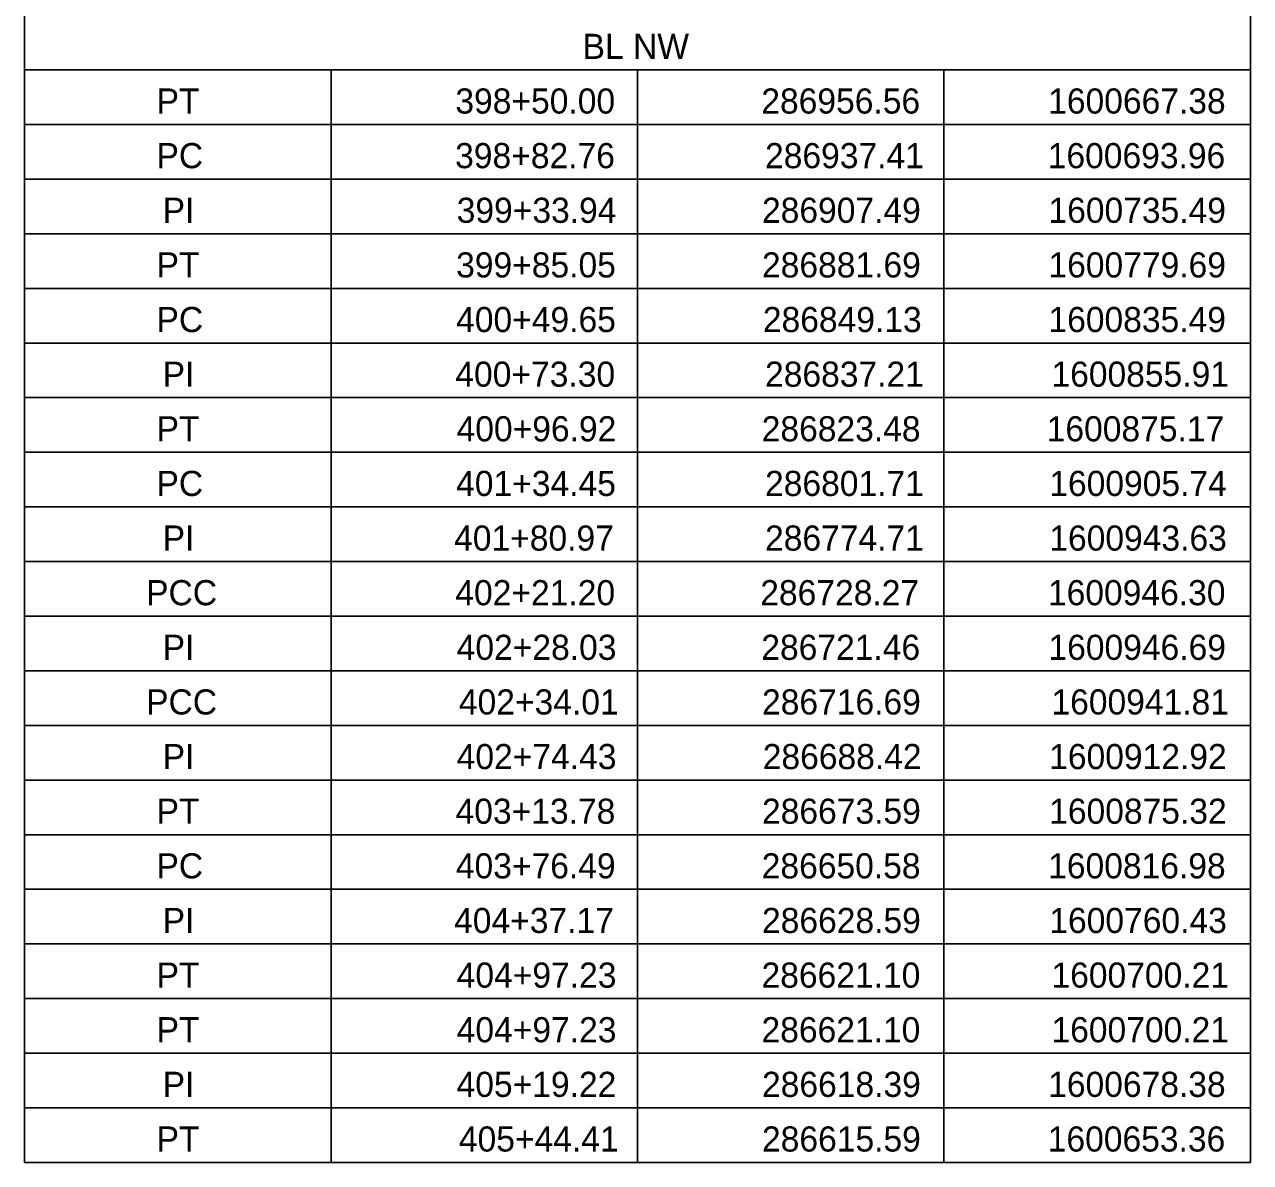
# Model space of a CAD drawing. Extents: x 0 to 34, y 0 to 22.
# Drawn here: x 9.33 to 16.16, y 7.8 to 14.14 of the extents above; entities that cross this region are included whole.
import ezdxf

# ---------------------------------------------------------------- set-up
doc = ezdxf.new("R2010")
doc.units = 0
doc.layers.add('SH_Text', color=7, linetype='Continuous')

msp = doc.modelspace()

# ---------------------------------------------------------------- linework, layer by layer
at = {"layer": 'SH_Text'}
for p, q in [((9.3309, 15.1087), (9.3309, 13.2826)), ((16.1618, 15.1087), (16.1618, 13.2826)), ((9.3309, 13.8913), (16.1618, 13.8913)), ((11.0386, 13.8913), (11.0386, 13.2826)), ((12.7464, 13.8913), (12.7464, 13.2826)), ((14.4541, 13.8913), (14.4541, 13.2826)), ((9.3309, 13.587), (16.1618, 13.587)), ((9.3309, 13.2826), (16.1618, 13.2826)), ((9.3309, 13.2826), (9.3309, 12.9783)), ((11.0386, 13.2826), (11.0386, 12.9783)), ((12.7464, 13.2826), (12.7464, 12.9783)), ((14.4541, 13.2826), (14.4541, 12.9783)), ((16.1618, 13.2826), (16.1618, 12.9783)), ((9.3309, 12.9783), (16.1618, 12.9783)), ((9.3309, 12.9783), (9.3309, 12.3696)), ((11.0386, 12.9783), (11.0386, 12.3696)), ((12.7464, 12.9783), (12.7464, 12.3696)), ((14.4541, 12.9783), (14.4541, 12.3696)), ((16.1618, 12.9783), (16.1618, 12.3696)), ((9.3309, 12.6739), (16.1618, 12.6739)), ((9.3309, 12.3696), (16.1618, 12.3696)), ((9.3309, 12.3696), (9.3309, 12.0652)), ((11.0386, 12.3696), (11.0386, 12.0652)), ((12.7464, 12.3696), (12.7464, 12.0652)), ((14.4541, 12.3696), (14.4541, 12.0652)), ((16.1618, 12.3696), (16.1618, 12.0652)), ((9.3309, 12.0652), (16.1618, 12.0652)), ((9.3309, 12.0652), (9.3309, 11.4565)), ((11.0386, 12.0652), (11.0386, 11.4565)), ((12.7464, 12.0652), (12.7464, 11.4565)), ((14.4541, 12.0652), (14.4541, 11.4565)), ((16.1618, 12.0652), (16.1618, 11.4565)), ((9.3309, 11.7609), (16.1618, 11.7609)), ((9.3309, 11.4565), (16.1618, 11.4565)), ((9.3309, 11.4565), (9.3309, 11.1522)), ((11.0386, 11.4565), (11.0386, 11.1522)), ((12.7464, 11.4565), (12.7464, 11.1522)), ((14.4541, 11.4565), (14.4541, 11.1522)), ((16.1618, 11.4565), (16.1618, 11.1522)), ((9.3309, 11.1522), (16.1618, 11.1522)), ((9.3309, 11.1522), (9.3309, 10.8478)), ((11.0386, 11.1522), (11.0386, 10.8478)), ((12.7464, 11.1522), (12.7464, 10.8478)), ((14.4541, 11.1522), (14.4541, 10.8478)), ((16.1618, 11.1522), (16.1618, 10.8478)), ((9.3309, 10.8478), (16.1618, 10.8478)), ((9.3309, 10.8478), (9.3309, 10.5435)), ((11.0386, 10.8478), (11.0386, 10.5435)), ((12.7464, 10.8478), (12.7464, 10.5435)), ((14.4541, 10.8478), (14.4541, 10.5435)), ((16.1618, 10.8478), (16.1618, 10.5435)), ((9.3309, 10.5435), (16.1618, 10.5435)), ((9.3309, 10.5435), (9.3309, 10.2391)), ((11.0386, 10.5435), (11.0386, 10.2391)), ((12.7464, 10.5435), (12.7464, 10.2391)), ((14.4541, 10.5435), (14.4541, 10.2391)), ((16.1618, 10.5435), (16.1618, 10.2391)), ((9.3309, 10.2391), (16.1618, 10.2391)), ((9.3309, 10.2391), (9.3309, 9.9348)), ((11.0386, 10.2391), (11.0386, 9.9348)), ((12.7464, 10.2391), (12.7464, 9.9348)), ((14.4541, 10.2391), (14.4541, 9.9348)), ((16.1618, 10.2391), (16.1618, 9.9348)), ((9.3309, 9.9348), (16.1618, 9.9348)), ((9.3309, 9.9348), (9.3309, 9.3261)), ((11.0386, 9.9348), (11.0386, 9.3261)), ((12.7464, 9.9348), (12.7464, 9.3261)), ((14.4541, 9.9348), (14.4541, 9.3261)), ((16.1618, 9.9348), (16.1618, 9.3261)), ((9.3309, 9.6304), (16.1618, 9.6304)), ((9.3309, 9.3261), (16.1618, 9.3261)), ((9.3309, 9.3261), (9.3309, 9.0217)), ((11.0386, 9.3261), (11.0386, 9.0217)), ((12.7464, 9.3261), (12.7464, 9.0217)), ((14.4541, 9.3261), (14.4541, 9.0217)), ((16.1618, 9.3261), (16.1618, 9.0217)), ((9.3309, 9.0217), (16.1618, 9.0217)), ((9.3309, 9.0217), (9.3309, 7.8043)), ((11.0386, 9.0217), (11.0386, 7.8043)), ((12.7464, 9.0217), (12.7464, 7.8043)), ((14.4541, 9.0217), (14.4541, 7.8043)), ((16.1618, 9.0217), (16.1618, 7.8043)), ((9.3309, 8.7174), (16.1618, 8.7174)), ((9.3309, 8.413), (16.1618, 8.413)), ((9.3309, 8.1087), (16.1618, 8.1087)), ((9.3309, 7.8043), (16.1618, 7.8043))]:
    msp.add_line(p, q, dxfattribs=at)
for points in [[(9.3309, 13.8913), (11.0386, 13.8913), (11.0386, 13.587), (9.3309, 13.587)], [(11.0386, 13.8913), (12.7464, 13.8913), (12.7464, 13.587), (11.0386, 13.587)], [(12.7464, 13.8913), (14.4541, 13.8913), (14.4541, 13.587), (12.7464, 13.587)], [(14.4541, 13.8913), (16.1618, 13.8913), (16.1618, 13.587), (14.4541, 13.587)], [(9.3309, 13.587), (11.0386, 13.587), (11.0386, 13.2826), (9.3309, 13.2826)], [(11.0386, 13.587), (12.7464, 13.587), (12.7464, 13.2826), (11.0386, 13.2826)], [(12.7464, 13.587), (14.4541, 13.587), (14.4541, 13.2826), (12.7464, 13.2826)], [(14.4541, 13.587), (16.1618, 13.587), (16.1618, 13.2826), (14.4541, 13.2826)], [(9.3309, 13.2826), (11.0386, 13.2826), (11.0386, 12.9783), (9.3309, 12.9783)], [(11.0386, 13.2826), (12.7464, 13.2826), (12.7464, 12.9783), (11.0386, 12.9783)], [(12.7464, 13.2826), (14.4541, 13.2826), (14.4541, 12.9783), (12.7464, 12.9783)], [(14.4541, 13.2826), (16.1618, 13.2826), (16.1618, 12.9783), (14.4541, 12.9783)], [(9.3309, 12.9783), (11.0386, 12.9783), (11.0386, 12.6739), (9.3309, 12.6739)], [(11.0386, 12.9783), (12.7464, 12.9783), (12.7464, 12.6739), (11.0386, 12.6739)], [(12.7464, 12.9783), (14.4541, 12.9783), (14.4541, 12.6739), (12.7464, 12.6739)], [(14.4541, 12.9783), (16.1618, 12.9783), (16.1618, 12.6739), (14.4541, 12.6739)], [(9.3309, 12.6739), (11.0386, 12.6739), (11.0386, 12.3696), (9.3309, 12.3696)], [(11.0386, 12.6739), (12.7464, 12.6739), (12.7464, 12.3696), (11.0386, 12.3696)], [(12.7464, 12.6739), (14.4541, 12.6739), (14.4541, 12.3696), (12.7464, 12.3696)], [(14.4541, 12.6739), (16.1618, 12.6739), (16.1618, 12.3696), (14.4541, 12.3696)], [(9.3309, 12.3696), (11.0386, 12.3696), (11.0386, 12.0652), (9.3309, 12.0652)], [(11.0386, 12.3696), (12.7464, 12.3696), (12.7464, 12.0652), (11.0386, 12.0652)], [(12.7464, 12.3696), (14.4541, 12.3696), (14.4541, 12.0652), (12.7464, 12.0652)], [(14.4541, 12.3696), (16.1618, 12.3696), (16.1618, 12.0652), (14.4541, 12.0652)], [(9.3309, 12.0652), (11.0386, 12.0652), (11.0386, 11.7609), (9.3309, 11.7609)], [(11.0386, 12.0652), (12.7464, 12.0652), (12.7464, 11.7609), (11.0386, 11.7609)], [(12.7464, 12.0652), (14.4541, 12.0652), (14.4541, 11.7609), (12.7464, 11.7609)], [(14.4541, 12.0652), (16.1618, 12.0652), (16.1618, 11.7609), (14.4541, 11.7609)], [(9.3309, 11.7609), (11.0386, 11.7609), (11.0386, 11.4565), (9.3309, 11.4565)], [(11.0386, 11.7609), (12.7464, 11.7609), (12.7464, 11.4565), (11.0386, 11.4565)], [(12.7464, 11.7609), (14.4541, 11.7609), (14.4541, 11.4565), (12.7464, 11.4565)], [(14.4541, 11.7609), (16.1618, 11.7609), (16.1618, 11.4565), (14.4541, 11.4565)], [(9.3309, 11.4565), (11.0386, 11.4565), (11.0386, 11.1522), (9.3309, 11.1522)], [(11.0386, 11.4565), (12.7464, 11.4565), (12.7464, 11.1522), (11.0386, 11.1522)], [(12.7464, 11.4565), (14.4541, 11.4565), (14.4541, 11.1522), (12.7464, 11.1522)], [(14.4541, 11.4565), (16.1618, 11.4565), (16.1618, 11.1522), (14.4541, 11.1522)], [(9.3309, 11.1522), (11.0386, 11.1522), (11.0386, 10.8478), (9.3309, 10.8478)], [(11.0386, 11.1522), (12.7464, 11.1522), (12.7464, 10.8478), (11.0386, 10.8478)], [(12.7464, 11.1522), (14.4541, 11.1522), (14.4541, 10.8478), (12.7464, 10.8478)], [(14.4541, 11.1522), (16.1618, 11.1522), (16.1618, 10.8478), (14.4541, 10.8478)], [(9.3309, 10.8478), (11.0386, 10.8478), (11.0386, 10.5435), (9.3309, 10.5435)], [(11.0386, 10.8478), (12.7464, 10.8478), (12.7464, 10.5435), (11.0386, 10.5435)], [(12.7464, 10.8478), (14.4541, 10.8478), (14.4541, 10.5435), (12.7464, 10.5435)], [(14.4541, 10.8478), (16.1618, 10.8478), (16.1618, 10.5435), (14.4541, 10.5435)], [(9.3309, 10.5435), (11.0386, 10.5435), (11.0386, 10.2391), (9.3309, 10.2391)], [(11.0386, 10.5435), (12.7464, 10.5435), (12.7464, 10.2391), (11.0386, 10.2391)], [(12.7464, 10.5435), (14.4541, 10.5435), (14.4541, 10.2391), (12.7464, 10.2391)], [(14.4541, 10.5435), (16.1618, 10.5435), (16.1618, 10.2391), (14.4541, 10.2391)], [(9.3309, 10.2391), (11.0386, 10.2391), (11.0386, 9.9348), (9.3309, 9.9348)], [(11.0386, 10.2391), (12.7464, 10.2391), (12.7464, 9.9348), (11.0386, 9.9348)], [(12.7464, 10.2391), (14.4541, 10.2391), (14.4541, 9.9348), (12.7464, 9.9348)], [(14.4541, 10.2391), (16.1618, 10.2391), (16.1618, 9.9348), (14.4541, 9.9348)], [(9.3309, 9.9348), (11.0386, 9.9348), (11.0386, 9.6304), (9.3309, 9.6304)], [(11.0386, 9.9348), (12.7464, 9.9348), (12.7464, 9.6304), (11.0386, 9.6304)], [(12.7464, 9.9348), (14.4541, 9.9348), (14.4541, 9.6304), (12.7464, 9.6304)], [(14.4541, 9.9348), (16.1618, 9.9348), (16.1618, 9.6304), (14.4541, 9.6304)], [(9.3309, 9.6304), (11.0386, 9.6304), (11.0386, 9.3261), (9.3309, 9.3261)], [(11.0386, 9.6304), (12.7464, 9.6304), (12.7464, 9.3261), (11.0386, 9.3261)], [(12.7464, 9.6304), (14.4541, 9.6304), (14.4541, 9.3261), (12.7464, 9.3261)], [(14.4541, 9.6304), (16.1618, 9.6304), (16.1618, 9.3261), (14.4541, 9.3261)], [(9.3309, 9.3261), (11.0386, 9.3261), (11.0386, 9.0217), (9.3309, 9.0217)], [(11.0386, 9.3261), (12.7464, 9.3261), (12.7464, 9.0217), (11.0386, 9.0217)], [(12.7464, 9.3261), (14.4541, 9.3261), (14.4541, 9.0217), (12.7464, 9.0217)], [(14.4541, 9.3261), (16.1618, 9.3261), (16.1618, 9.0217), (14.4541, 9.0217)], [(9.3309, 9.0217), (11.0386, 9.0217), (11.0386, 8.7174), (9.3309, 8.7174)], [(11.0386, 9.0217), (12.7464, 9.0217), (12.7464, 8.7174), (11.0386, 8.7174)], [(12.7464, 9.0217), (14.4541, 9.0217), (14.4541, 8.7174), (12.7464, 8.7174)], [(14.4541, 9.0217), (16.1618, 9.0217), (16.1618, 8.7174), (14.4541, 8.7174)], [(9.3309, 8.7174), (11.0386, 8.7174), (11.0386, 8.413), (9.3309, 8.413)], [(11.0386, 8.7174), (12.7464, 8.7174), (12.7464, 8.413), (11.0386, 8.413)], [(12.7464, 8.7174), (14.4541, 8.7174), (14.4541, 8.413), (12.7464, 8.413)], [(14.4541, 8.7174), (16.1618, 8.7174), (16.1618, 8.413), (14.4541, 8.413)], [(9.3309, 8.413), (11.0386, 8.413), (11.0386, 8.1087), (9.3309, 8.1087)], [(11.0386, 8.413), (12.7464, 8.413), (12.7464, 8.1087), (11.0386, 8.1087)], [(12.7464, 8.413), (14.4541, 8.413), (14.4541, 8.1087), (12.7464, 8.1087)], [(14.4541, 8.413), (16.1618, 8.413), (16.1618, 8.1087), (14.4541, 8.1087)], [(9.3309, 8.1087), (11.0386, 8.1087), (11.0386, 7.8043), (9.3309, 7.8043)], [(11.0386, 8.1087), (12.7464, 8.1087), (12.7464, 7.8043), (11.0386, 7.8043)], [(12.7464, 8.1087), (14.4541, 8.1087), (14.4541, 7.8043), (12.7464, 7.8043)], [(14.4541, 8.1087), (16.1618, 8.1087), (16.1618, 7.8043), (14.4541, 7.8043)]]:
    msp.add_lwpolyline(points, close=True, dxfattribs=at)

# ---------------------------------------------------------------- texts
for s, p in [('BL NW', (12.4405, 13.9522)), ('PT', (10.0668, 13.6478)), ('398+50.00', (11.7315, 13.6478)), ('286956.56', (13.4362, 13.6478)), ('1600667.38', (15.0345, 13.6478)), ('PC', (10.0661, 13.3435)), ('398+82.76', (11.7303, 13.3435)), ('286937.41', (13.457, 13.3435)), ('1600693.96', (15.0322, 13.3435)), ('PI', (10.1005, 13.0391)), ('399+33.94', (11.739, 13.0391)), ('286907.49', (13.4401, 13.0391)), ('1600735.49', (15.0361, 13.0391)), ('PT', (10.0668, 12.7348)), ('399+85.05', (11.7357, 12.7348)), ('286881.69', (13.4401, 12.7348)), ('1600779.69', (15.0361, 12.7348)), ('PC', (10.0661, 12.4304)), ('400+49.65', (11.7357, 12.4304)), ('286849.13', (13.4449, 12.4304)), ('1600835.49', (15.0361, 12.4304)), ('PI', (10.1005, 12.1261)), ('400+73.30', (11.7315, 12.1261)), ('286837.21', (13.457, 12.1261)), ('1600855.91', (15.0529, 12.1261)), ('PT', (10.0668, 11.8217)), ('400+96.92', (11.7382, 11.8217)), ('286823.48', (13.4385, 11.8217)), ('1600875.17', (15.0264, 11.8217)), ('PC', (10.0661, 11.5174)), ('401+34.45', (11.7357, 11.5174)), ('286801.71', (13.457, 11.5174)), ('1600905.74', (15.0409, 11.5174)), ('PI', (10.1005, 11.213)), ('401+80.97', (11.7245, 11.213)), ('286774.71', (13.457, 11.213)), ('1600943.63', (15.0409, 11.213)), ('PCC', (10.0085, 10.9087)), ('402+21.20', (11.7315, 10.9087)), ('286728.27', (13.4304, 10.9087)), ('1600946.30', (15.0334, 10.9087)), ('PI', (10.1005, 10.6043)), ('402+28.03', (11.739, 10.6043)), ('286721.46', (13.4362, 10.6043)), ('1600946.69', (15.0361, 10.6043)), ('PCC', (10.0085, 10.3)), ('402+34.01', (11.7511, 10.3)), ('286716.69', (13.4401, 10.3)), ('1600941.81', (15.0529, 10.3)), ('PI', (10.1005, 9.9957)), ('402+74.43', (11.739, 9.9957)), ('286688.42', (13.4441, 9.9957)), ('1600912.92', (15.0401, 9.9957)), ('PT', (10.0668, 9.6913)), ('403+13.78', (11.7327, 9.6913)), ('286673.59', (13.4401, 9.6913)), ('1600875.32', (15.0401, 9.6913)), ('PC', (10.0661, 9.387)), ('403+76.49', (11.7342, 9.387)), ('286650.58', (13.4385, 9.387)), ('1600816.98', (15.0345, 9.387)), ('PI', (10.1005, 9.0826)), ('404+37.17', (11.7245, 9.0826)), ('286628.59', (13.4401, 9.0826)), ('1600760.43', (15.0409, 9.0826)), ('PT', (10.0668, 8.7783)), ('404+97.23', (11.739, 8.7783)), ('286621.10', (13.4374, 8.7783)), ('1600700.21', (15.0529, 8.7783)), ('PT', (10.0668, 8.4739)), ('404+97.23', (11.739, 8.4739)), ('286621.10', (13.4374, 8.4739)), ('1600700.21', (15.0529, 8.4739)), ('PI', (10.1005, 8.1696)), ('405+19.22', (11.7382, 8.1696)), ('286618.39', (13.4401, 8.1696)), ('1600678.38', (15.0345, 8.1696)), ('PT', (10.0668, 7.8652)), ('405+44.41', (11.7511, 7.8652)), ('286615.59', (13.4401, 7.8652)), ('1600653.36', (15.0322, 7.8652))]:
    msp.add_text(s, height=0.14, dxfattribs=at).set_placement(p)

doc.saveas('drawing.dxf')
